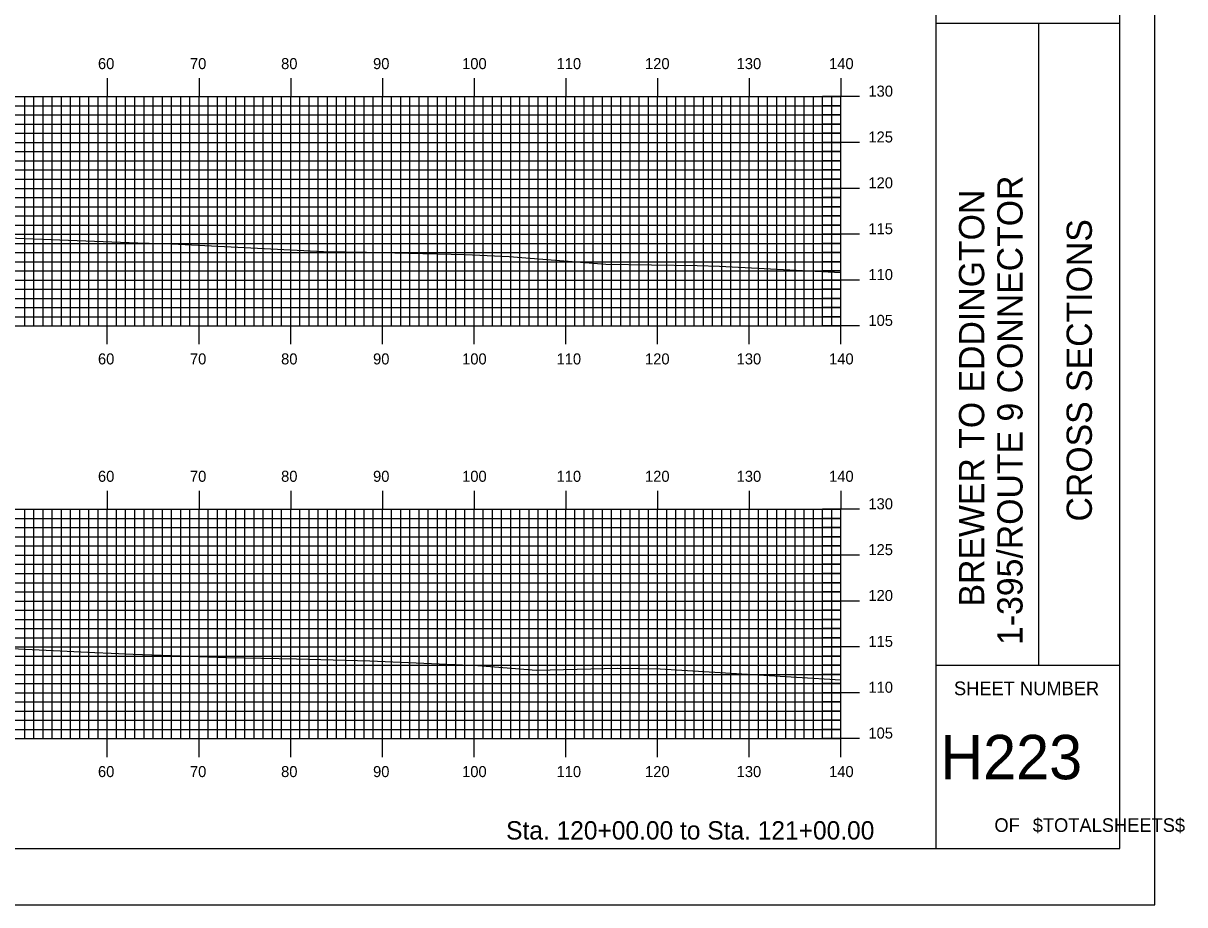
# Model space of a CAD drawing. Extents: x 1772022 to 1772366, y 442591 to 442811.
# Drawn here: x 1772238.9 to 1772365.6, y 442590.5 to 442686.7 of the extents above; entities that cross this region are included whole.
import ezdxf

# ---------------------------------------------------------------- set-up
doc = ezdxf.new("R2010")
doc.units = 0
for name, color, linetype in [('BORDER', 7, 'Continuous'), ('H_V ANNOTATION', 7, 'Continuous'), ('MAJOR', 7, 'Continuous'), ('MINOR', 7, 'Continuous'), ('PLOT BOUNDARY', 7, 'Continuous'), ('S_Roadway_Centerline', 7, 'Continuous')]:
    doc.layers.add(name, color=color, linetype=linetype)

msp = doc.modelspace()

# ---------------------------------------------------------------- linework, layer by layer
at = {"layer": 'BORDER'}
for p, q in [((1772338.49, 442596.67), (1772338.49, 442806.67)), ((1772338.49, 442686.67), (1772358.49, 442686.67)), ((1772349.68, 442616.67), (1772349.68, 442686.67)), ((1772338.49, 442616.67), (1772358.49, 442616.67))]:
    msp.add_line(p, q, dxfattribs=at)
msp.add_lwpolyline([(1772038.49, 442596.67), (1772358.49, 442596.67), (1772358.49, 442806.67), (1772038.49, 442806.67)], close=True, dxfattribs=at)
at = {"layer": 'MAJOR'}
for p, q in [((1772248.09, 442680.67), (1772248.09, 442678.67)), ((1772258.09, 442680.67), (1772258.09, 442678.67)), ((1772268.09, 442680.67), (1772268.09, 442678.67)), ((1772278.09, 442680.67), (1772278.09, 442678.67)), ((1772288.09, 442680.67), (1772288.09, 442678.67)), ((1772298.09, 442680.67), (1772298.09, 442678.67)), ((1772308.09, 442680.67), (1772308.09, 442678.67)), ((1772318.09, 442680.67), (1772318.09, 442678.67)), ((1772328.09, 442680.67), (1772328.09, 442678.67)), ((1772048.09, 442678.67), (1772328.09, 442678.67)), ((1772048.09, 442678.67), (1772328.09, 442678.67)), ((1772248.09, 442653.67), (1772248.09, 442678.67)), ((1772258.09, 442653.67), (1772258.09, 442678.67)), ((1772268.09, 442653.67), (1772268.09, 442678.67)), ((1772278.09, 442653.67), (1772278.09, 442678.67)), ((1772288.09, 442653.67), (1772288.09, 442678.67)), ((1772298.09, 442653.67), (1772298.09, 442678.67)), ((1772308.09, 442653.67), (1772308.09, 442678.67)), ((1772318.09, 442653.67), (1772318.09, 442678.67)), ((1772330.1, 442678.67), (1772326.09, 442678.67)), ((1772328.09, 442653.67), (1772328.09, 442678.67)), ((1772328.09, 442653.67), (1772328.09, 442678.67)), ((1772048.09, 442673.67), (1772328.09, 442673.67)), ((1772330.1, 442673.67), (1772326.09, 442673.67)), ((1772048.09, 442668.67), (1772328.09, 442668.67)), ((1772330.1, 442668.67), (1772326.09, 442668.67)), ((1772048.09, 442663.67), (1772328.09, 442663.67)), ((1772330.1, 442663.67), (1772326.09, 442663.67)), ((1772048.09, 442658.67), (1772328.09, 442658.67)), ((1772330.1, 442658.67), (1772326.09, 442658.67)), ((1772048.09, 442653.67), (1772328.09, 442653.67)), ((1772048.09, 442653.67), (1772328.09, 442653.67)), ((1772248.09, 442651.66), (1772248.09, 442653.67)), ((1772258.09, 442651.66), (1772258.09, 442653.67)), ((1772268.09, 442651.66), (1772268.09, 442653.67)), ((1772278.09, 442651.66), (1772278.09, 442653.67)), ((1772288.09, 442651.66), (1772288.09, 442653.67)), ((1772298.09, 442651.66), (1772298.09, 442653.67)), ((1772308.09, 442651.66), (1772308.09, 442653.67)), ((1772318.09, 442651.66), (1772318.09, 442653.67)), ((1772330.1, 442653.67), (1772326.09, 442653.67)), ((1772328.09, 442651.66), (1772328.09, 442653.67)), ((1772248.09, 442635.67), (1772248.09, 442633.67)), ((1772258.09, 442635.67), (1772258.09, 442633.67)), ((1772268.09, 442635.67), (1772268.09, 442633.67)), ((1772278.09, 442635.67), (1772278.09, 442633.67)), ((1772288.09, 442635.67), (1772288.09, 442633.67)), ((1772298.09, 442635.67), (1772298.09, 442633.67)), ((1772308.09, 442635.67), (1772308.09, 442633.67)), ((1772318.09, 442635.67), (1772318.09, 442633.67)), ((1772328.09, 442635.67), (1772328.09, 442633.67)), ((1772048.09, 442633.67), (1772328.09, 442633.67)), ((1772048.09, 442633.67), (1772328.09, 442633.67)), ((1772248.09, 442608.67), (1772248.09, 442633.67)), ((1772258.09, 442608.67), (1772258.09, 442633.67)), ((1772268.09, 442608.67), (1772268.09, 442633.67)), ((1772278.09, 442608.67), (1772278.09, 442633.67)), ((1772288.09, 442608.67), (1772288.09, 442633.67)), ((1772298.09, 442608.67), (1772298.09, 442633.67)), ((1772308.09, 442608.67), (1772308.09, 442633.67)), ((1772318.09, 442608.67), (1772318.09, 442633.67)), ((1772330.1, 442633.67), (1772326.09, 442633.67)), ((1772328.09, 442608.67), (1772328.09, 442633.67)), ((1772328.09, 442608.67), (1772328.09, 442633.67)), ((1772048.09, 442628.67), (1772328.09, 442628.67)), ((1772330.1, 442628.67), (1772326.09, 442628.67)), ((1772048.09, 442623.67), (1772328.09, 442623.67)), ((1772330.1, 442623.67), (1772326.09, 442623.67)), ((1772048.09, 442618.67), (1772328.09, 442618.67)), ((1772330.1, 442618.67), (1772326.09, 442618.67)), ((1772048.09, 442613.67), (1772328.09, 442613.67)), ((1772330.1, 442613.67), (1772326.09, 442613.67)), ((1772048.09, 442608.67), (1772328.09, 442608.67)), ((1772048.09, 442608.67), (1772328.09, 442608.67)), ((1772248.09, 442606.66), (1772248.09, 442608.67)), ((1772258.09, 442606.66), (1772258.09, 442608.67)), ((1772268.09, 442606.66), (1772268.09, 442608.67)), ((1772278.09, 442606.66), (1772278.09, 442608.67)), ((1772288.09, 442606.66), (1772288.09, 442608.67)), ((1772298.09, 442606.66), (1772298.09, 442608.67)), ((1772308.09, 442606.66), (1772308.09, 442608.67)), ((1772318.09, 442606.66), (1772318.09, 442608.67)), ((1772330.1, 442608.67), (1772326.09, 442608.67)), ((1772328.09, 442606.66), (1772328.09, 442608.67))]:
    msp.add_line(p, q, dxfattribs=at)
at = {"layer": 'MINOR'}
for p, q in [((1772239.09, 442653.67), (1772239.09, 442678.67)), ((1772240.09, 442653.67), (1772240.09, 442678.67)), ((1772241.09, 442653.67), (1772241.09, 442678.67)), ((1772242.09, 442653.67), (1772242.09, 442678.67)), ((1772243.09, 442653.67), (1772243.09, 442678.67)), ((1772244.09, 442653.67), (1772244.09, 442678.67)), ((1772245.09, 442653.67), (1772245.09, 442678.67)), ((1772246.09, 442653.67), (1772246.09, 442678.67)), ((1772247.09, 442653.67), (1772247.09, 442678.67)), ((1772249.09, 442653.67), (1772249.09, 442678.67)), ((1772250.09, 442653.67), (1772250.09, 442678.67)), ((1772251.09, 442653.67), (1772251.09, 442678.67)), ((1772252.09, 442653.67), (1772252.09, 442678.67)), ((1772253.09, 442653.67), (1772253.09, 442678.67)), ((1772254.09, 442653.67), (1772254.09, 442678.67)), ((1772255.09, 442653.67), (1772255.09, 442678.67)), ((1772256.09, 442653.67), (1772256.09, 442678.67)), ((1772257.09, 442653.67), (1772257.09, 442678.67)), ((1772259.09, 442653.67), (1772259.09, 442678.67)), ((1772260.09, 442653.67), (1772260.09, 442678.67)), ((1772261.09, 442653.67), (1772261.09, 442678.67)), ((1772262.09, 442653.67), (1772262.09, 442678.67)), ((1772263.09, 442653.67), (1772263.09, 442678.67)), ((1772264.09, 442653.67), (1772264.09, 442678.67)), ((1772265.09, 442653.67), (1772265.09, 442678.67)), ((1772266.09, 442653.67), (1772266.09, 442678.67)), ((1772267.09, 442653.67), (1772267.09, 442678.67)), ((1772269.09, 442653.67), (1772269.09, 442678.67)), ((1772270.09, 442653.67), (1772270.09, 442678.67)), ((1772271.09, 442653.67), (1772271.09, 442678.67)), ((1772272.09, 442653.67), (1772272.09, 442678.67)), ((1772273.09, 442653.67), (1772273.09, 442678.67)), ((1772274.09, 442653.67), (1772274.09, 442678.67)), ((1772275.09, 442653.67), (1772275.09, 442678.67)), ((1772276.09, 442653.67), (1772276.09, 442678.67)), ((1772277.09, 442653.67), (1772277.09, 442678.67)), ((1772279.09, 442653.67), (1772279.09, 442678.67)), ((1772280.09, 442653.67), (1772280.09, 442678.67)), ((1772281.09, 442653.67), (1772281.09, 442678.67)), ((1772282.09, 442653.67), (1772282.09, 442678.67)), ((1772283.09, 442653.67), (1772283.09, 442678.67)), ((1772284.09, 442653.67), (1772284.09, 442678.67)), ((1772285.09, 442653.67), (1772285.09, 442678.67)), ((1772286.09, 442653.67), (1772286.09, 442678.67)), ((1772287.09, 442653.67), (1772287.09, 442678.67)), ((1772289.09, 442653.67), (1772289.09, 442678.67)), ((1772290.09, 442653.67), (1772290.09, 442678.67)), ((1772291.09, 442653.67), (1772291.09, 442678.67)), ((1772292.09, 442653.67), (1772292.09, 442678.67)), ((1772293.09, 442653.67), (1772293.09, 442678.67)), ((1772294.09, 442653.67), (1772294.09, 442678.67)), ((1772295.09, 442653.67), (1772295.09, 442678.67)), ((1772296.09, 442653.67), (1772296.09, 442678.67)), ((1772297.09, 442653.67), (1772297.09, 442678.67)), ((1772299.09, 442653.67), (1772299.09, 442678.67)), ((1772300.09, 442653.67), (1772300.09, 442678.67)), ((1772301.09, 442653.67), (1772301.09, 442678.67)), ((1772302.09, 442653.67), (1772302.09, 442678.67)), ((1772303.09, 442653.67), (1772303.09, 442678.67)), ((1772304.09, 442653.67), (1772304.09, 442678.67)), ((1772305.09, 442653.67), (1772305.09, 442678.67)), ((1772306.09, 442653.67), (1772306.09, 442678.67)), ((1772307.09, 442653.67), (1772307.09, 442678.67)), ((1772309.09, 442653.67), (1772309.09, 442678.67)), ((1772310.09, 442653.67), (1772310.09, 442678.67)), ((1772311.09, 442653.67), (1772311.09, 442678.67)), ((1772312.09, 442653.67), (1772312.09, 442678.67)), ((1772313.09, 442653.67), (1772313.09, 442678.67)), ((1772314.09, 442653.67), (1772314.09, 442678.67)), ((1772315.09, 442653.67), (1772315.09, 442678.67)), ((1772316.09, 442653.67), (1772316.09, 442678.67)), ((1772317.09, 442653.67), (1772317.09, 442678.67)), ((1772319.09, 442653.67), (1772319.09, 442678.67)), ((1772320.09, 442653.67), (1772320.09, 442678.67)), ((1772321.09, 442653.67), (1772321.09, 442678.67)), ((1772322.09, 442653.67), (1772322.09, 442678.67)), ((1772323.09, 442653.67), (1772323.09, 442678.67)), ((1772324.09, 442653.67), (1772324.09, 442678.67)), ((1772325.09, 442653.67), (1772325.09, 442678.67)), ((1772326.09, 442653.67), (1772326.09, 442678.67)), ((1772327.09, 442653.67), (1772327.09, 442678.67)), ((1772048.09, 442677.67), (1772328.09, 442677.67)), ((1772328.09, 442677.67), (1772326.09, 442677.67)), ((1772048.09, 442676.67), (1772328.09, 442676.67)), ((1772328.09, 442676.67), (1772326.09, 442676.67)), ((1772048.09, 442675.67), (1772328.09, 442675.67)), ((1772328.09, 442675.67), (1772326.09, 442675.67)), ((1772048.09, 442674.67), (1772328.09, 442674.67)), ((1772328.09, 442674.67), (1772326.09, 442674.67)), ((1772048.09, 442672.67), (1772328.09, 442672.67)), ((1772328.09, 442672.67), (1772326.09, 442672.67)), ((1772048.09, 442671.67), (1772328.09, 442671.67)), ((1772328.09, 442671.67), (1772326.09, 442671.67)), ((1772048.09, 442670.67), (1772328.09, 442670.67)), ((1772328.09, 442670.67), (1772326.09, 442670.67)), ((1772048.09, 442669.67), (1772328.09, 442669.67)), ((1772328.09, 442669.67), (1772326.09, 442669.67)), ((1772048.09, 442667.67), (1772328.09, 442667.67)), ((1772328.09, 442667.67), (1772326.09, 442667.67)), ((1772048.09, 442666.67), (1772328.09, 442666.67)), ((1772328.09, 442666.67), (1772326.09, 442666.67)), ((1772048.09, 442665.67), (1772328.09, 442665.67)), ((1772048.09, 442664.67), (1772328.09, 442664.67)), ((1772328.09, 442665.67), (1772326.09, 442665.67)), ((1772328.09, 442664.67), (1772326.09, 442664.67)), ((1772048.09, 442662.67), (1772328.09, 442662.67)), ((1772328.09, 442662.67), (1772326.09, 442662.67)), ((1772048.09, 442661.67), (1772328.09, 442661.67)), ((1772328.09, 442661.67), (1772326.09, 442661.67)), ((1772048.09, 442660.67), (1772328.09, 442660.67)), ((1772048.09, 442659.67), (1772328.09, 442659.67)), ((1772328.09, 442660.67), (1772326.09, 442660.67)), ((1772328.09, 442659.67), (1772326.09, 442659.67)), ((1772048.09, 442657.67), (1772328.09, 442657.67)), ((1772328.09, 442657.67), (1772326.09, 442657.67)), ((1772048.09, 442656.67), (1772328.09, 442656.67)), ((1772328.09, 442656.67), (1772326.09, 442656.67)), ((1772048.09, 442655.67), (1772328.09, 442655.67)), ((1772048.09, 442654.67), (1772328.09, 442654.67)), ((1772328.09, 442655.67), (1772326.09, 442655.67)), ((1772328.09, 442654.67), (1772326.09, 442654.67)), ((1772239.09, 442608.67), (1772239.09, 442633.67)), ((1772240.09, 442608.67), (1772240.09, 442633.67)), ((1772241.09, 442608.67), (1772241.09, 442633.67)), ((1772242.09, 442608.67), (1772242.09, 442633.67)), ((1772243.09, 442608.67), (1772243.09, 442633.67)), ((1772244.09, 442608.67), (1772244.09, 442633.67)), ((1772245.09, 442608.67), (1772245.09, 442633.67)), ((1772246.09, 442608.67), (1772246.09, 442633.67)), ((1772247.09, 442608.67), (1772247.09, 442633.67)), ((1772249.09, 442608.67), (1772249.09, 442633.67)), ((1772250.09, 442608.67), (1772250.09, 442633.67)), ((1772251.09, 442608.67), (1772251.09, 442633.67)), ((1772252.09, 442608.67), (1772252.09, 442633.67)), ((1772253.09, 442608.67), (1772253.09, 442633.67)), ((1772254.09, 442608.67), (1772254.09, 442633.67)), ((1772255.09, 442608.67), (1772255.09, 442633.67)), ((1772256.09, 442608.67), (1772256.09, 442633.67)), ((1772257.09, 442608.67), (1772257.09, 442633.67)), ((1772259.09, 442608.67), (1772259.09, 442633.67)), ((1772260.09, 442608.67), (1772260.09, 442633.67)), ((1772261.09, 442608.67), (1772261.09, 442633.67)), ((1772262.09, 442608.67), (1772262.09, 442633.67)), ((1772263.09, 442608.67), (1772263.09, 442633.67)), ((1772264.09, 442608.67), (1772264.09, 442633.67)), ((1772265.09, 442608.67), (1772265.09, 442633.67)), ((1772266.09, 442608.67), (1772266.09, 442633.67)), ((1772267.09, 442608.67), (1772267.09, 442633.67)), ((1772269.09, 442608.67), (1772269.09, 442633.67)), ((1772270.09, 442608.67), (1772270.09, 442633.67)), ((1772271.09, 442608.67), (1772271.09, 442633.67)), ((1772272.09, 442608.67), (1772272.09, 442633.67)), ((1772273.09, 442608.67), (1772273.09, 442633.67)), ((1772274.09, 442608.67), (1772274.09, 442633.67)), ((1772275.09, 442608.67), (1772275.09, 442633.67)), ((1772276.09, 442608.67), (1772276.09, 442633.67)), ((1772277.09, 442608.67), (1772277.09, 442633.67)), ((1772279.09, 442608.67), (1772279.09, 442633.67)), ((1772280.09, 442608.67), (1772280.09, 442633.67)), ((1772281.09, 442608.67), (1772281.09, 442633.67)), ((1772282.09, 442608.67), (1772282.09, 442633.67)), ((1772283.09, 442608.67), (1772283.09, 442633.67)), ((1772284.09, 442608.67), (1772284.09, 442633.67)), ((1772285.09, 442608.67), (1772285.09, 442633.67)), ((1772286.09, 442608.67), (1772286.09, 442633.67)), ((1772287.09, 442608.67), (1772287.09, 442633.67)), ((1772289.09, 442608.67), (1772289.09, 442633.67)), ((1772290.09, 442608.67), (1772290.09, 442633.67)), ((1772291.09, 442608.67), (1772291.09, 442633.67)), ((1772292.09, 442608.67), (1772292.09, 442633.67)), ((1772293.09, 442608.67), (1772293.09, 442633.67)), ((1772294.09, 442608.67), (1772294.09, 442633.67)), ((1772295.09, 442608.67), (1772295.09, 442633.67)), ((1772296.09, 442608.67), (1772296.09, 442633.67)), ((1772297.09, 442608.67), (1772297.09, 442633.67)), ((1772299.09, 442608.67), (1772299.09, 442633.67)), ((1772300.09, 442608.67), (1772300.09, 442633.67)), ((1772301.09, 442608.67), (1772301.09, 442633.67)), ((1772302.09, 442608.67), (1772302.09, 442633.67)), ((1772303.09, 442608.67), (1772303.09, 442633.67)), ((1772304.09, 442608.67), (1772304.09, 442633.67)), ((1772305.09, 442608.67), (1772305.09, 442633.67)), ((1772306.09, 442608.67), (1772306.09, 442633.67)), ((1772307.09, 442608.67), (1772307.09, 442633.67)), ((1772309.09, 442608.67), (1772309.09, 442633.67)), ((1772310.09, 442608.67), (1772310.09, 442633.67)), ((1772311.09, 442608.67), (1772311.09, 442633.67)), ((1772312.09, 442608.67), (1772312.09, 442633.67)), ((1772313.09, 442608.67), (1772313.09, 442633.67)), ((1772314.09, 442608.67), (1772314.09, 442633.67)), ((1772315.09, 442608.67), (1772315.09, 442633.67)), ((1772316.09, 442608.67), (1772316.09, 442633.67)), ((1772317.09, 442608.67), (1772317.09, 442633.67)), ((1772319.09, 442608.67), (1772319.09, 442633.67)), ((1772320.09, 442608.67), (1772320.09, 442633.67)), ((1772321.09, 442608.67), (1772321.09, 442633.67)), ((1772322.09, 442608.67), (1772322.09, 442633.67)), ((1772323.09, 442608.67), (1772323.09, 442633.67)), ((1772324.09, 442608.67), (1772324.09, 442633.67)), ((1772325.09, 442608.67), (1772325.09, 442633.67)), ((1772326.09, 442608.67), (1772326.09, 442633.67)), ((1772327.09, 442608.67), (1772327.09, 442633.67)), ((1772048.09, 442632.67), (1772328.09, 442632.67)), ((1772328.09, 442632.67), (1772326.09, 442632.67)), ((1772048.09, 442631.67), (1772328.09, 442631.67)), ((1772048.09, 442630.67), (1772328.09, 442630.67)), ((1772328.09, 442631.67), (1772326.09, 442631.67)), ((1772328.09, 442630.67), (1772326.09, 442630.67)), ((1772048.09, 442629.67), (1772328.09, 442629.67)), ((1772328.09, 442629.67), (1772326.09, 442629.67)), ((1772048.09, 442627.67), (1772328.09, 442627.67)), ((1772048.09, 442626.67), (1772328.09, 442626.67)), ((1772328.09, 442627.67), (1772326.09, 442627.67)), ((1772328.09, 442626.67), (1772326.09, 442626.67)), ((1772048.09, 442625.67), (1772328.09, 442625.67)), ((1772328.09, 442625.67), (1772326.09, 442625.67)), ((1772048.09, 442624.67), (1772328.09, 442624.67)), ((1772328.09, 442624.67), (1772326.09, 442624.67)), ((1772048.09, 442622.67), (1772328.09, 442622.67)), ((1772048.09, 442621.67), (1772328.09, 442621.67)), ((1772328.09, 442622.67), (1772326.09, 442622.67)), ((1772328.09, 442621.67), (1772326.09, 442621.67)), ((1772048.09, 442620.67), (1772328.09, 442620.67)), ((1772328.09, 442620.67), (1772326.09, 442620.67)), ((1772048.09, 442619.67), (1772328.09, 442619.67)), ((1772328.09, 442619.67), (1772326.09, 442619.67)), ((1772048.09, 442617.67), (1772328.09, 442617.67)), ((1772048.09, 442616.67), (1772328.09, 442616.67)), ((1772328.09, 442617.67), (1772326.09, 442617.67)), ((1772328.09, 442616.67), (1772326.09, 442616.67)), ((1772048.09, 442615.67), (1772328.09, 442615.67)), ((1772328.09, 442615.67), (1772326.09, 442615.67)), ((1772048.09, 442614.67), (1772328.09, 442614.67)), ((1772328.09, 442614.67), (1772326.09, 442614.67)), ((1772048.09, 442612.67), (1772328.09, 442612.67)), ((1772048.09, 442611.67), (1772328.09, 442611.67)), ((1772328.09, 442612.67), (1772326.09, 442612.67)), ((1772328.09, 442611.67), (1772326.09, 442611.67)), ((1772048.09, 442610.67), (1772328.09, 442610.67)), ((1772328.09, 442610.67), (1772326.09, 442610.67)), ((1772048.09, 442609.67), (1772328.09, 442609.67)), ((1772328.09, 442609.67), (1772326.09, 442609.67))]:
    msp.add_line(p, q, dxfattribs=at)
at = {"layer": 'PLOT BOUNDARY'}
msp.add_lwpolyline([(1772022.31, 442590.55), (1772362.31, 442590.55), (1772362.31, 442810.55), (1772022.31, 442810.55)], close=True, dxfattribs=at)
at = {"layer": 'S_Roadway_Centerline'}
for points in [[(1772232.48, 442663.44), (1772251.4, 442662.74), (1772255.13, 442662.62), (1772271.68, 442661.79), (1772276.35, 442661.71), (1772287.1, 442661.44), (1772291.92, 442661.22), (1772302.46, 442660.41), (1772312.4, 442660.26), (1772314.84, 442660.18), (1772328.09, 442659.5)], [(1772236.06, 442618.55), (1772246.73, 442618.04), (1772248.5, 442617.97), (1772250.92, 442617.86), (1772261.11, 442617.5), (1772268.72, 442617.38), (1772276.71, 442617.16), (1772288.5, 442616.64), (1772294.91, 442616.14), (1772303.76, 442616.33), (1772308.38, 442616.26), (1772323.26, 442615.37), (1772328.09, 442615.09)]]:
    msp.add_lwpolyline(points, dxfattribs=at)

# ---------------------------------------------------------------- texts
at = {"layer": 'BORDER'}
for s, p in [('1-395/ROUTE 9 CONNECTOR', (1772347.9, 442618.87)), ('BREWER TO EDDINGTON', (1772343.72, 442623.07)), ('CROSS SECTIONS', (1772355.46, 442632.34))]:
    msp.add_text(s, height=2.7557, rotation=90, dxfattribs=at).set_placement(p)
for s, height, p in [('SHEET NUMBER', 1.4905, (1772340.42, 442613.4)), ('H223', 4.839, (1772338.93, 442604.23)), ('$TOTALSHEETS$', 1.4905, (1772349.01, 442598.49)), ('OF', 1.491, (1772344.83, 442598.49))]:
    msp.add_text(s, height=height, dxfattribs=at).set_placement(p)
at = {"layer": 'H_V ANNOTATION'}
for s, height, p in [('60', 1.2, (1772247.07, 442681.67)), ('70', 1.2, (1772257.1, 442681.67)), ('80', 1.2, (1772267.04, 442681.67)), ('90', 1.2, (1772277.07, 442681.67)), ('100', 1.2, (1772286.78, 442681.67)), ('110', 1.2, (1772297.08, 442681.67)), ('120', 1.2, (1772306.73, 442681.67)), ('130', 1.2, (1772316.72, 442681.67)), ('140', 1.2, (1772326.8, 442681.67)), ('130', 1.2, (1772331.09, 442678.67)), ('125', 1.2, (1772331.09, 442673.67)), ('120', 1.2, (1772331.09, 442668.67)), ('115', 1.2, (1772331.09, 442663.67)), ('110', 1.2, (1772331.09, 442658.67)), ('105', 1.2, (1772331.09, 442653.67)), ('60', 1.2, (1772247.07, 442649.47)), ('70', 1.2, (1772257.1, 442649.47)), ('80', 1.2, (1772267.04, 442649.47)), ('90', 1.2, (1772277.07, 442649.47)), ('100', 1.2, (1772286.78, 442649.47)), ('110', 1.2, (1772297.08, 442649.47)), ('120', 1.2, (1772306.73, 442649.47)), ('130', 1.2, (1772316.72, 442649.47)), ('140', 1.2, (1772326.8, 442649.47)), ('60', 1.2, (1772247.07, 442636.67)), ('70', 1.2, (1772257.1, 442636.67)), ('80', 1.2, (1772267.04, 442636.67)), ('90', 1.2, (1772277.07, 442636.67)), ('100', 1.2, (1772286.78, 442636.67)), ('110', 1.2, (1772297.08, 442636.67)), ('120', 1.2, (1772306.73, 442636.67)), ('130', 1.2, (1772316.72, 442636.67)), ('140', 1.2, (1772326.8, 442636.67)), ('130', 1.2, (1772331.09, 442633.67)), ('125', 1.2, (1772331.09, 442628.67)), ('120', 1.2, (1772331.09, 442623.67)), ('115', 1.2, (1772331.09, 442618.67)), ('110', 1.2, (1772331.09, 442613.67)), ('105', 1.2, (1772331.09, 442608.67)), ('60', 1.2, (1772247.07, 442604.47)), ('70', 1.2, (1772257.1, 442604.47)), ('80', 1.2, (1772267.04, 442604.47)), ('90', 1.2, (1772277.07, 442604.47)), ('100', 1.2, (1772286.78, 442604.47)), ('110', 1.2, (1772297.08, 442604.47)), ('120', 1.2, (1772306.73, 442604.47)), ('130', 1.2, (1772316.72, 442604.47)), ('140', 1.2, (1772326.8, 442604.47)), ('Sta. 120+00.00 to Sta. 121+00.00', 2.0004, (1772291.58, 442597.66))]:
    msp.add_text(s, height=height, dxfattribs=at).set_placement(p)

doc.saveas('drawing.dxf')
